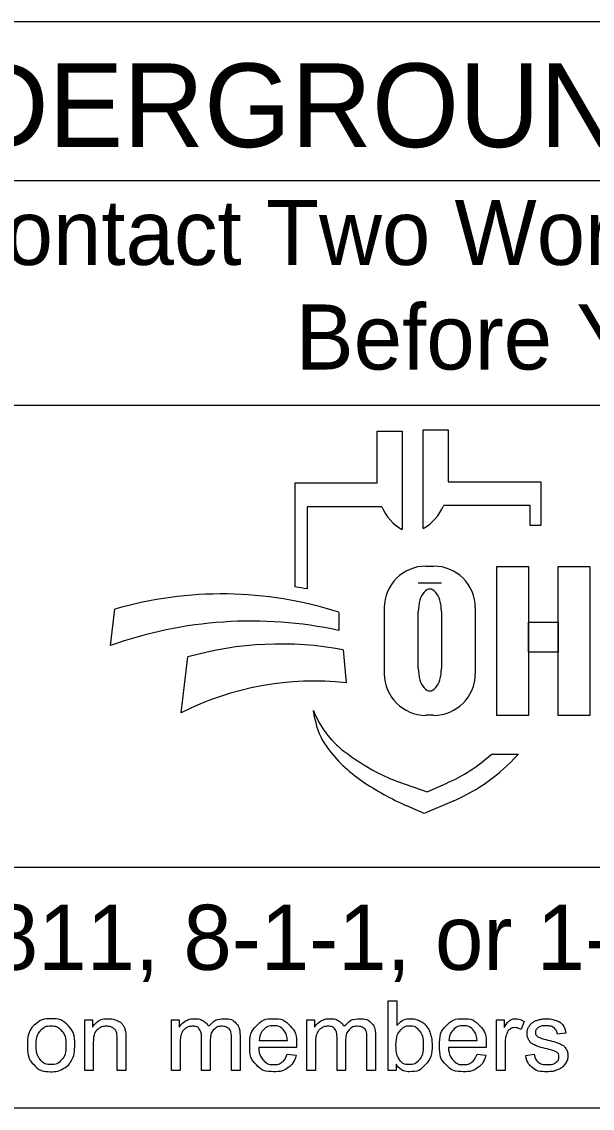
# Model space of a CAD drawing. Extents: x 0 to 34, y 0 to 22.
# Drawn here: x 2.624 to 3.851, y 2.488 to 4.826 of the extents above; entities that cross this region are included whole.
import ezdxf

# ---------------------------------------------------------------- set-up
doc = ezdxf.new("R2010")
doc.units = 0
doc.layers.add('SH_Data', color=7, linetype='Continuous')
doc.layers.add('SH_Text', color=7, linetype='Continuous')

msp = doc.modelspace()

# ---------------------------------------------------------------- linework, layer by layer
at = {"layer": 'SH_Data'}
for p, q in [((6.2826, 4.8256), (2.0326, 4.8256)), ((2.0326, 4.484), (6.2826, 4.484)), ((2.0326, 4.0006), (6.2826, 4.0006)), ((6.2826, 3.006), (2.0326, 3.006)), ((6.2826, 2.4881), (2.0326, 2.4881))]:
    msp.add_line(p, q, dxfattribs=at)
at = {"layer": 'SH_Text'}
for p, q in [((3.3886, 3.8336), (3.3886, 3.9451)), ((3.3886, 3.9451), (3.4423, 3.9451)), ((3.4423, 3.9451), (3.4423, 3.733)), ((3.4879, 3.7353), (3.4879, 3.9474)), ((3.4879, 3.9474), (3.5416, 3.9474)), ((3.5416, 3.9474), (3.5416, 3.8359)), ((3.2127, 3.6097), (3.2127, 3.8336)), ((3.2127, 3.8336), (3.3886, 3.8336)), ((3.5416, 3.8359), (3.7408, 3.8359)), ((3.7408, 3.8359), (3.7408, 3.7421)), ((3.2379, 3.7821), (3.2379, 3.6053)), ((3.399, 3.7821), (3.2379, 3.7821)), ((3.7175, 3.7845), (3.5312, 3.7845)), ((3.7175, 3.7421), (3.7175, 3.7845)), ((3.7408, 3.7421), (3.7175, 3.7421)), ((3.4936, 3.6544), (3.5102, 3.6544)), ((3.5269, 3.6174), (3.4771, 3.6174)), ((2.8153, 3.4834), (2.8247, 3.5615)), ((3.306, 3.555), (3.306, 3.5162)), ((3.4042, 3.4229), (3.4042, 3.5649)), ((3.4771, 3.4343), (3.4771, 3.5567)), ((3.5269, 3.5567), (3.5269, 3.4343)), ((3.5996, 3.5649), (3.5996, 3.4229)), ((3.3159, 3.4744), (3.3222, 3.4035)), ((2.9671, 3.3389), (2.9818, 3.459)), ((3.2548, 3.326), (3.2518, 3.3439)), ((3.5102, 3.3335), (3.4936, 3.3335)), ((3.6351, 3.2501), (3.6925, 3.2501)), ((3.4367, 3.1897), (3.4961, 3.1692)), ((3.4961, 3.1692), (3.5371, 3.187)), ((3.4901, 3.1222), (3.4527, 3.1387)), ((3.5534, 3.1497), (3.4901, 3.1222))]:
    msp.add_line(p, q, dxfattribs=at)
for points in [[(3.646, 3.6534), (3.714, 3.6534), (3.714, 3.3334), (3.646, 3.3334)], [(3.7782, 3.6534), (3.8462, 3.6534), (3.8462, 3.3334), (3.7782, 3.3334)], [(3.714, 3.5335), (3.7782, 3.5335), (3.7782, 3.4695), (3.714, 3.4695)]]:
    msp.add_lwpolyline(points, close=True, dxfattribs=at)
for points in [[(3.4294, 2.5692), (3.4124, 2.5692), (3.4124, 2.7194), (3.4308, 2.7194), (3.4308, 2.6659)], [(2.7599, 2.5692), (2.7599, 2.6781), (2.7765, 2.6781), (2.7765, 2.6626)], [(2.9463, 2.5692), (2.9463, 2.6781), (2.9628, 2.6781), (2.9628, 2.6627)], [(3.2377, 2.5692), (3.2377, 2.6781), (3.2542, 2.6781), (3.2542, 2.6627)], [(3.6455, 2.5692), (3.6455, 2.6781), (3.6621, 2.6781), (3.6621, 2.6616)], [(3.7045, 2.6746), (3.6981, 2.6575)], [(3.0938, 2.6439), (3.0938, 2.5692), (3.0754, 2.5692), (3.0754, 2.6377)], [(3.3852, 2.6439), (3.3852, 2.5692), (3.3668, 2.5692), (3.3668, 2.6377)], [(3.7945, 2.6499), (3.7764, 2.6475)], [(2.7783, 2.6286), (2.7783, 2.5692), (2.7599, 2.5692)], [(2.8483, 2.6361), (2.8483, 2.5692), (2.8298, 2.5692), (2.8298, 2.6354)], [(2.9648, 2.6256), (2.9648, 2.5692), (2.9463, 2.5692)], [(3.0294, 2.6324), (3.0294, 2.5692), (3.011, 2.5692), (3.011, 2.6399)], [(3.2151, 2.6189), (3.1339, 2.6189)], [(3.135, 2.634), (3.1957, 2.634)], [(3.2561, 2.6256), (3.2561, 2.5692), (3.2377, 2.5692)], [(3.3208, 2.6324), (3.3208, 2.5692), (3.3024, 2.5692), (3.3024, 2.6399)], [(3.6231, 2.6189), (3.5419, 2.6189)], [(3.5429, 2.634), (3.6037, 2.634)], [(3.6639, 2.6262), (3.6639, 2.5692), (3.6455, 2.5692)], [(3.1955, 2.6044), (3.2146, 2.602)], [(3.6035, 2.6044), (3.6226, 2.602)], [(3.7081, 2.6017), (3.7263, 2.6046)], [(3.4294, 2.5828), (3.4294, 2.5692)]]:
    msp.add_lwpolyline(points, dxfattribs=at)
for centre, radius, start, end in [((3.4904, 3.8189), 0.0985, 201.9296, 240.7469), ((3.4398, 3.8212), 0.0985, 299.2531, 338.0704), ((3.4936, 3.5649), 0.0895, 90, 180), ((3.5102, 3.5649), 0.0895, 0, 90), ((3.0845, 2.8007), 0.8191, 79.2074, 81.0007), ((3.0548, 2.7755), 0.8191, 72.1402, 106.3144), ((3.1178, 2.6443), 0.8919, 77.8238, 109.8274), ((3.1817, 2.7547), 0.7322, 79.44, 105.8467), ((3.4936, 3.4229), 0.0895, 180, 270), ((3.5102, 3.4229), 0.0895, 270, 0), ((3.2538, 2.7715), 0.6357, 83.8248, 116.8021), ((3.4391, 3.416), 0.2008, 201.0457, 232.5314), ((3.3961, 3.3501), 0.1433, 189.6817, 216.0884), ((3.5298, 3.4475), 0.3088, 216.0884, 235.7167), ((3.6317, 3.6672), 0.5173, 232.5314, 241.794), ((3.3937, 3.5175), 0.3602, 293.4582, 312.0712), ((3.3937, 3.5175), 0.401, 293.4582, 317.8286), ((3.5465, 3.5084), 0.3371, 241.794, 250.9821), ((3.6963, 3.6918), 0.6044, 235.7167, 246.2325)]:
    msp.add_arc(centre, radius, start, end, dxfattribs=at)
for centre, start_param, end_param in [((3.502, 3.5567), 4.712389, 7.853982), ((3.502, 3.4343), 1.570796, 4.712389)]:
    msp.add_ellipse(centre, major_axis=(0, 0.0484), ratio=0.514403, start_param=start_param, end_param=end_param, dxfattribs=at)
for points in [[(2.6364, 2.6236), (2.6364, 2.6538), (2.6532, 2.6684), (2.6672, 2.6805), (2.6874, 2.6805), (2.7098, 2.6805), (2.7241, 2.6658), (2.7383, 2.6511), (2.7383, 2.6252), (2.7383, 2.6042), (2.732, 2.5922), (2.7257, 2.5801), (2.7137, 2.5735), (2.7016, 2.5668), (2.6874, 2.5668), (2.6646, 2.5668), (2.6505, 2.5815), (2.6364, 2.5961), (2.6364, 2.6236)], [(2.6554, 2.6236), (2.6554, 2.6027), (2.6645, 2.5923), (2.6736, 2.5819), (2.6874, 2.5819), (2.7011, 2.5819), (2.7102, 2.5924), (2.7193, 2.6028), (2.7193, 2.6242), (2.7193, 2.6444), (2.7101, 2.6548), (2.701, 2.6652), (2.6874, 2.6652), (2.6736, 2.6652), (2.6645, 2.6549), (2.6554, 2.6445), (2.6554, 2.6236)], [(2.7765, 2.6626), (2.7885, 2.6805), (2.8111, 2.6805), (2.8209, 2.6805), (2.8292, 2.6769), (2.8374, 2.6734), (2.8415, 2.6677), (2.8456, 2.6619), (2.8472, 2.654), (2.8483, 2.6489), (2.8483, 2.6361)], [(2.9628, 2.6627), (2.9679, 2.6707), (2.9764, 2.6756), (2.9849, 2.6805), (2.9958, 2.6805), (3.0079, 2.6805), (3.0156, 2.6754), (3.0234, 2.6704), (3.0265, 2.6614), (3.0395, 2.6805), (3.0602, 2.6805), (3.0764, 2.6805), (3.0851, 2.6715), (3.0938, 2.6625), (3.0938, 2.6439)], [(3.2146, 2.602), (3.2101, 2.5853), (3.1979, 2.576), (3.1857, 2.5668), (3.1667, 2.5668), (3.1429, 2.5668), (3.1289, 2.5815), (3.1149, 2.5962), (3.1149, 2.6227), (3.1149, 2.6502), (3.1291, 2.6653), (3.1432, 2.6805), (3.1657, 2.6805), (3.1875, 2.6805), (3.2014, 2.6656), (3.2152, 2.6508), (3.2152, 2.6238), (3.2152, 2.6222), (3.2151, 2.6189)], [(3.1957, 2.634), (3.1945, 2.6478), (3.1888, 2.6547), (3.1799, 2.6654), (3.1659, 2.6654), (3.1532, 2.6654), (3.1445, 2.6568), (3.1359, 2.6483), (3.135, 2.634)], [(3.2542, 2.6627), (3.2593, 2.6707), (3.2678, 2.6756), (3.2763, 2.6805), (3.2872, 2.6805), (3.2993, 2.6805), (3.307, 2.6754), (3.3147, 2.6704), (3.3179, 2.6614), (3.3308, 2.6805), (3.3516, 2.6805), (3.3678, 2.6805), (3.3765, 2.6715), (3.3852, 2.6625), (3.3852, 2.6439)], [(3.4292, 2.6245), (3.4292, 2.6049), (3.4345, 2.5962), (3.4432, 2.5819), (3.458, 2.5819), (3.4701, 2.5819), (3.4789, 2.5924), (3.4877, 2.6029), (3.4877, 2.6237), (3.4877, 2.6451), (3.4792, 2.6552), (3.4708, 2.6654), (3.4588, 2.6654), (3.4468, 2.6654), (3.438, 2.6548), (3.4292, 2.6443), (3.4292, 2.6245)], [(3.4308, 2.6659), (3.4425, 2.6805), (3.4606, 2.6805), (3.4706, 2.6805), (3.4796, 2.6764), (3.4885, 2.6724), (3.4943, 2.6651), (3.5001, 2.6577), (3.5034, 2.6474), (3.5067, 2.6371), (3.5067, 2.6253), (3.5067, 2.5973), (3.4928, 2.5821), (3.479, 2.5668), (3.4596, 2.5668), (3.4404, 2.5668), (3.4294, 2.5828)], [(3.6226, 2.602), (3.618, 2.5853), (3.6059, 2.576), (3.5937, 2.5668), (3.5747, 2.5668), (3.5509, 2.5668), (3.5369, 2.5815), (3.5229, 2.5962), (3.5229, 2.6227), (3.5229, 2.6502), (3.537, 2.6653), (3.5512, 2.6805), (3.5737, 2.6805), (3.5955, 2.6805), (3.6093, 2.6656), (3.6232, 2.6508), (3.6232, 2.6238), (3.6232, 2.6222), (3.6231, 2.6189)], [(3.6037, 2.634), (3.6025, 2.6478), (3.5967, 2.6547), (3.5879, 2.6654), (3.5739, 2.6654), (3.5612, 2.6654), (3.5525, 2.6568), (3.5439, 2.6483), (3.5429, 2.634)], [(3.6621, 2.6616), (3.6684, 2.6731), (3.6738, 2.6768), (3.6792, 2.6805), (3.6856, 2.6805), (3.6949, 2.6805), (3.7045, 2.6746)], [(3.7764, 2.6475), (3.7752, 2.6559), (3.7693, 2.6606), (3.7634, 2.6654), (3.7526, 2.6654), (3.7399, 2.6654), (3.7345, 2.6611), (3.729, 2.6569), (3.729, 2.6513), (3.729, 2.6477), (3.7313, 2.6448), (3.7335, 2.6419), (3.7384, 2.6399), (3.7411, 2.6389), (3.7547, 2.6352), (3.7743, 2.63), (3.782, 2.6266), (3.7898, 2.6233), (3.7942, 2.617), (3.7986, 2.6106), (3.7986, 2.6012), (3.7986, 2.592), (3.7932, 2.5839), (3.7878, 2.5757), (3.7777, 2.5713), (3.7675, 2.5668), (3.7547, 2.5668), (3.7334, 2.5668), (3.7223, 2.5756), (3.7112, 2.5844), (3.7081, 2.6017)], [(3.7263, 2.6046), (3.7278, 2.5936), (3.7349, 2.5878), (3.7419, 2.5819), (3.7545, 2.5819), (3.7673, 2.5819), (3.7734, 2.5871), (3.7796, 2.5923), (3.7796, 2.5993), (3.7796, 2.6055), (3.7742, 2.6091), (3.7704, 2.6116), (3.7553, 2.6154), (3.735, 2.6205), (3.7271, 2.6242), (3.7193, 2.628), (3.7152, 2.6346), (3.7112, 2.6412), (3.7112, 2.6491), (3.7112, 2.6564), (3.7145, 2.6626), (3.7178, 2.6688), (3.7236, 2.6729), (3.7279, 2.6761), (3.7353, 2.6783), (3.7428, 2.6805), (3.7513, 2.6805), (3.7641, 2.6805), (3.7738, 2.6768), (3.7835, 2.6731), (3.7881, 2.6668), (3.7927, 2.6605), (3.7945, 2.6499)], [(2.8298, 2.6354), (2.8298, 2.6466), (2.8277, 2.6522), (2.8255, 2.6578), (2.8201, 2.6611), (2.8146, 2.6644), (2.8072, 2.6644), (2.7954, 2.6644), (2.7869, 2.657), (2.7783, 2.6495), (2.7783, 2.6286)], [(3.011, 2.6399), (3.011, 2.6522), (3.0065, 2.6583), (3.002, 2.6644), (2.9917, 2.6644), (2.9839, 2.6644), (2.9773, 2.6603), (2.9707, 2.6562), (2.9677, 2.6484), (2.9648, 2.6405), (2.9648, 2.6256)], [(3.0754, 2.6377), (3.0754, 2.6488), (3.0736, 2.6536), (3.0718, 2.6585), (3.0671, 2.6615), (3.0624, 2.6644), (3.0561, 2.6644), (3.0446, 2.6644), (3.037, 2.6568), (3.0294, 2.6492), (3.0294, 2.6324)], [(3.3024, 2.6399), (3.3024, 2.6522), (3.2979, 2.6583), (3.2933, 2.6644), (3.2831, 2.6644), (3.2753, 2.6644), (3.2687, 2.6603), (3.2621, 2.6562), (3.2591, 2.6484), (3.2561, 2.6405), (3.2561, 2.6256)], [(3.3668, 2.6377), (3.3668, 2.6488), (3.365, 2.6536), (3.3632, 2.6585), (3.3585, 2.6615), (3.3538, 2.6644), (3.3474, 2.6644), (3.336, 2.6644), (3.3284, 2.6568), (3.3208, 2.6492), (3.3208, 2.6324)], [(3.6981, 2.6575), (3.6914, 2.6615), (3.6846, 2.6615), (3.6786, 2.6615), (3.6738, 2.6578), (3.669, 2.6542), (3.667, 2.6477), (3.6639, 2.6379), (3.6639, 2.6262)], [(3.1339, 2.6189), (3.1349, 2.601), (3.1441, 2.5914), (3.1532, 2.5819), (3.1668, 2.5819), (3.177, 2.5819), (3.1841, 2.5873), (3.1913, 2.5926), (3.1955, 2.6044)], [(3.5419, 2.6189), (3.5429, 2.601), (3.5521, 2.5914), (3.5612, 2.5819), (3.5748, 2.5819), (3.585, 2.5819), (3.5921, 2.5873), (3.5993, 2.5926), (3.6035, 2.6044)]]:
    msp.add_open_spline(points, degree=3, dxfattribs=at)

# ---------------------------------------------------------------- texts
for s, height, p in [('UNDERGROUND UTILITIES', 0.18, (2.1607, 4.5559)), ('Contact Two Working Days', 0.14, (2.4522, 4.3024)), ('Before You Dig', 0.14, (3.2134, 4.0774)), ('OHIO811, 8-1-1, or 1-800-362-2764', 0.14, (2.0771, 2.7859))]:
    msp.add_text(s, height=height, dxfattribs=at).set_placement(p)

doc.saveas('drawing.dxf')
